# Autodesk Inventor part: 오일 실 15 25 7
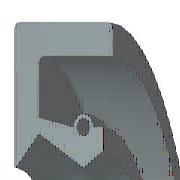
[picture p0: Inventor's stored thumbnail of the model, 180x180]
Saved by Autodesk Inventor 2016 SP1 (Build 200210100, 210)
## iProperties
Created: 2012-02
Part Number: 오일 실 15 25 7
Material: 고무
Description: 오일-실
Document SubType Name: Modeling
Standard: KS B 2804
Designer: mduedu
Standards Organization: KS
Language: ko-KR
Size Designation: D - 15 25 7
Categories: <MemberInstance><Categories><Category DisplayName="샤프트 부품" InternalName="7f7aeb1f-a693-4053-b835-cee3144e0d98" Mnemonic="SHFT"><Category DisplayName="실링" Intern
Density: 0.93 g/cm^3
Appearance: 고무 - 검은색 - 버전 1.1
IsCustomPart: 1
Author: mduedu
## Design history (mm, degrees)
revolve "본체" stored, may be unused: angle "d17" = 90 deg
revolve "스프링1" stored, may be unused: angle "d18" = 90 deg
body "Solid1"
sketch "스케치1"
  geometry: L1 (0, 12.5)-(7, 12.5); L2 (7, 10.75)-(1.75, 10.75); L3 (1.75, 9.25)-(4.9, 7.5); L4 (4.9, 7.5)-(0, 7.5); L5 (0, 0)-(9.586, 0) reference; L6 (4.9, 7.5)-(6.3, 8.375); L7 (0, 18)-(0, -3) reference; L8 (-1.941, 0)-(11.507, 0) reference; L9 (4.2, 9.6)-(1.75, 10.09); L10 (1.75, 10.09)-(1.75, 10.75); L11 (0, 12.5)-(0, 7.588); L12 (4.9, 7.5)-(0, 7.5); L13 (1.75, 9.25)-(0.152, 7.528); L14 (7, 12.5)-(7, 10.75); L15 (5.6, 9.6)-(6.3, 9.6); L16 (6.3, 9.6)-(6.3, 8.375); C1 r 0.455 at (4.9, 9.6); A1 r 0.7 centre (4.9, 9.6) between (5.6, 9.6) and (4.2, 9.6); A2 r 0.088 centre (0.088, 7.588) between (0, 7.588) and (0.152, 7.528); 1 further point
  constraints: 28 end point, 5 horizontal alignment, 5 point on line, 4 point on circle, 4 vertical alignment, 3 centre point, 3 tangent, 2 collinear, 2 horizontal, 2 perpendicular, 1 coincident, 1 parallel
  dimensions: "d0" = 25 diameter of L1 L5 (= SD2); "d1" = 1.75 distance of L1.end L2.start (= SD); "d2" = 0.91 diameter of C1 (= SPDI); "d3" = 1.4 diameter of A1 (= SPDA); "d4" = 15 diameter of L3.end L5 (= NND); "d5" = 18.5 diameter of L3.start L5 (= TKDM); "d7" = 20.18 diameter of L9.end L5 (= TKDM + 0.24 x SWDT); "d8" = 1.75 distance between parallel lines of L11 L10 (= SD); "d9" = 4.9 distance from line of L11 C1.centre (= SPDST); "d10" = 19.2 diameter of C1.centre L5 (= HLDM); "d11" = 0.0875 radius of A2 (= 0.25 x LAB); "d12" = 6.3 distance between parallel lines of L11 L16 (= SDI); "d13" = 16.75 diameter of L6.end L5 (= ABDM); "d14" = 7 distance from line of L11 L1.end (= SWDT)
fillet "모깎기1" dims "d6" = 0.3 (= RR)
other parameters: "SD2" = 25 [user parameter; used in 1 equation term], "SWDT" = 7 [user parameter; used in 2 equation terms], "RR" = 0.3 [user parameter; used in 1 equation term], "SD" = 1.75 [user parameter; used in 2 equation terms], "NND" = 15 [user parameter; used in 1 equation term], "SPDA" = 1.4 [user parameter; used in 1 equation term], "SPDI" = 0.91 [user parameter; used in 1 equation term], "TKDM" = 18.5 [user parameter; used in 2 equation terms], "HLDM" = 19.2 [user parameter; used in 1 equation term], "ABDM" = 16.75 [user parameter; used in 1 equation term], "SDI" = 6.3 [user parameter; used in 1 equation term], "SPDST" = 4.9 [user parameter; used in 1 equation term], "LAB" = 0.35 [user parameter; used in 1 equation term], "d15" = 0, "d16" = 0, "d19" = 0
